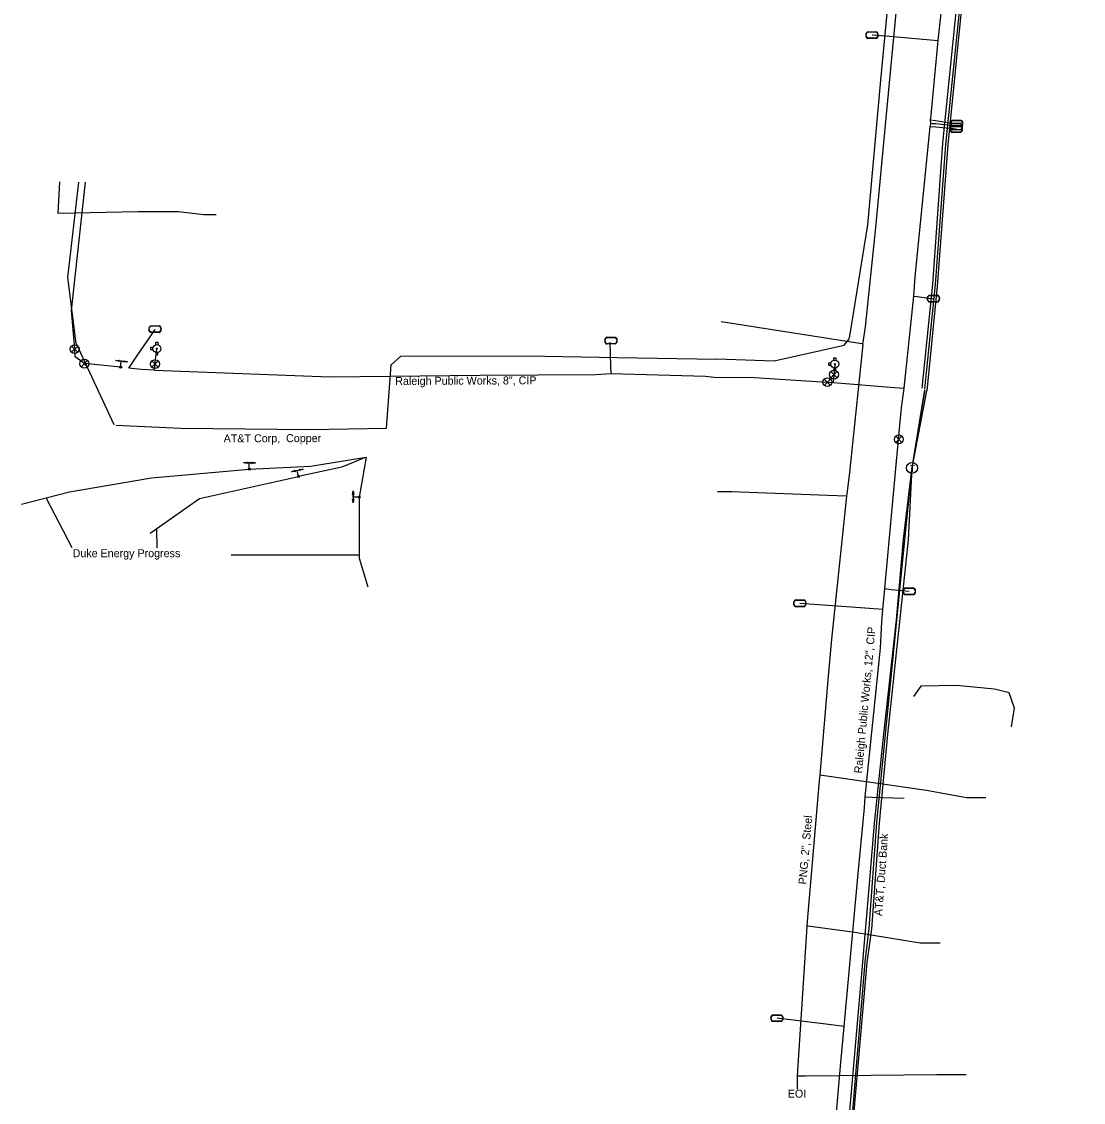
# Model space of a CAD drawing. Extents: x 2070721 to 2083039, y 729290 to 737883.
# Drawn here: x 2081990 to 2082520, y 736699 to 737239 of the extents above; entities that cross this region are included whole.
import ezdxf

# ---------------------------------------------------------------- set-up
doc = ezdxf.new("R2010")
doc.units = 0
for name, color, linetype in [('COGO Default Point Elevation', 7, 'Continuous'), ('COGO Default Point Number', 7, 'Continuous'), ('Exist Utilities Gas UG Line SUE Cogo Point CELL', 7, 'Continuous'), ('Exist Utilities Gas UG Line SUE LOS B Cogo Comment', 7, 'Continuous'), ('Exist Utilities Power Pole CELL', 7, 'Continuous'), ('Exist Utilities Power Pole Cogo Elevation', 7, 'Continuous'), ('Exist Utilities Power UG Cable Cogo Point CELL', 7, 'Continuous'), ('Exist Utilities Power UG Cable SUE LOS B Cogo Elevation', 7, 'Continuous'), ('Exist Utilities Power UG Cable SUE LOS B Cogo Number', 7, 'Continuous'), ('Exist Utilities Telephone Hand Hole Cogo Number', 7, 'Continuous'), ('Exist Utilities Telephone Manhole CELL', 7, 'Continuous'), ('Exist Utilities Telephone UG Cable SUE LOS C Cogo Point CELL', 7, 'Continuous'), ('Exist Utilities Telephone UG FO Cogo Point CELL', 7, 'Continuous'), ('Exist Utilities TV Pedestal Cogo Elevation', 7, 'Continuous'), ('Exist Utilities TV Pedestal Cogo Number', 7, 'Continuous'), ('Exist Utilities TV UG Cable Cogo Point CELL', 7, 'Continuous'), ('Exist Utilities TV UG Cable SUE LOS C Cogo Comment', 7, 'Continuous'), ('Exist Utilities TV UG Cable SUE LOS C Cogo Point CELL', 7, 'Continuous'), ('Exist Utilities Water Meter Cogo Elevation', 7, 'Continuous'), ('Exist Utilities Water Meter Cogo Number', 7, 'Continuous')]:
    doc.layers.add(name, color=color, linetype=linetype)

msp = doc.modelspace()

# ---------------------------------------------------------------- linework, layer by layer
at = {"layer": 'COGO Default Point Elevation'}
for points in [[(2082017.65, 737077.06), (2082014.5, 737073.91), (2082016.07, 737075.48), (2082017.65, 737073.91), (2082014.5, 737077.06)], [(2082022.46, 737069.81), (2082019.3, 737066.66), (2082020.88, 737068.23), (2082022.46, 737066.66), (2082019.3, 737069.81)], [(2082057.81, 737069.57), (2082054.67, 737066.42), (2082056.24, 737067.99), (2082057.81, 737066.42), (2082054.67, 737069.57)], [(2082397.16, 737064.34), (2082394.01, 737061.19), (2082395.59, 737062.77), (2082397.16, 737061.19), (2082394.01, 737064.34)], [(2082393.85, 737060.55), (2082390.7, 737057.4), (2082392.28, 737058.98), (2082393.85, 737057.4), (2082390.7, 737060.55)], [(2082429.58, 737031.97), (2082426.43, 737028.82), (2082428, 737030.39), (2082429.58, 737028.82), (2082426.43, 737031.97)]]:
    msp.add_lwpolyline(points, dxfattribs=at)
for centre in [(2082016.07, 737075.48), (2082020.88, 737068.23), (2082056.24, 737067.99), (2082392.28, 737058.98), (2082395.59, 737062.77), (2082428, 737030.39)]:
    msp.add_circle(centre, 2.23, dxfattribs=at)
at = {"layer": 'COGO Default Point Number'}
for p, q in [((2082057.16, 737075.79), (2082057.16, 737075.79)), ((2082395.99, 737068), (2082395.99, 737068))]:
    msp.add_line(p, q, dxfattribs=at)
for points in [[(2082056.65, 737077.7), (2082056.65, 737078.99), (2082057.67, 737078.99), (2082057.67, 737077.68)], [(2082055.25, 737076.3), (2082053.96, 737076.3), (2082053.96, 737075.28), (2082055.25, 737075.28)], [(2082056.65, 737073.88), (2082056.65, 737072.59), (2082057.67, 737072.59), (2082057.67, 737073.9)], [(2082394.08, 737068.52), (2082392.79, 737068.52), (2082392.79, 737067.49), (2082394.08, 737067.49)], [(2082395.48, 737069.92), (2082395.48, 737071.2), (2082396.5, 737071.2), (2082396.5, 737069.89)], [(2082395.48, 737066.09), (2082395.48, 737064.8), (2082396.5, 737064.8), (2082396.5, 737066.12)]]:
    msp.add_lwpolyline(points, dxfattribs=at)
for centre, radius in [((2082057.16, 737075.79), 1.98), ((2082057.16, 737075.79), 0.243), ((2082395.99, 737068), 1.98), ((2082395.99, 737068), 0.243)]:
    msp.add_circle(centre, radius, dxfattribs=at)
at = {"layer": 'Exist Utilities Power Pole CELL'}
for points in [[(2082439.59, 737056.02), (2082445.06, 737108.02), (2082449.98, 737178.42), (2082461.23, 737288.47), (2082468.24, 737363.11), (2082475.86, 737428.31), (2082486.51, 737547.46), (2082488.71, 737576.37), (2082496.01, 737653.67), (2082500.6, 737701.89), (2082514.35, 737824.3), (2082518.96, 737879.18)], [(2082442.18, 737054.68), (2082447.39, 737106.94), (2082452.67, 737177.7), (2082463.63, 737288.2), (2082470.01, 737364.08), (2082471.45, 737371.14), (2082477.93, 737428.92), (2082490.82, 737576.45), (2082502.28, 737701.6), (2082515.51, 737824.17), (2082520.25, 737879.05)], [(2082396.3, 736612.75), (2082410.09, 736769.04), (2082413.73, 736812.06), (2082415.9, 736838.6), (2082420.43, 736883.01), (2082426.83, 736940.19), (2082430.34, 736980.56), (2082434.54, 737015.35), (2082440.98, 737055.09)], [(2082398.47, 736612.36), (2082412.17, 736768.95), (2082414.49, 736785.54), (2082418.32, 736838.61), (2082422.49, 736882.86), (2082432.87, 736980.11), (2082434.6, 737016.15), (2082441.99, 737054.65)]]:
    msp.add_lwpolyline(points, dxfattribs=at)
at = {"layer": 'Exist Utilities Power Pole Cogo Elevation'}
for points in [[(2081989.55, 736997.93), (2082013.53, 737004.14), (2082054.43, 737011.2), (2082103.34, 737015.52)], [(2082053.87, 736983.53), (2082078.41, 737000.75), (2082127.92, 737011.84)], [(2082158.3, 737001.5), (2082158.3, 736971.08), (2082162.61, 736956.68)]]:
    msp.add_lwpolyline(points, dxfattribs=at)
at = {"layer": 'Exist Utilities Power UG Cable Cogo Point CELL'}
for p, q in [((2082106.48, 737018.6), (2082100.51, 737018.6)), ((2082103.34, 737015.52), (2082103.34, 737018.6)), ((2082103.34, 737018.6), (2082106.48, 737018.6)), ((2082103.34, 737015.52), (2082103.34, 737015.52)), ((2082130.31, 737015.54), (2082124.49, 737014.23)), ((2082127.25, 737014.85), (2082130.31, 737015.54)), ((2082127.92, 737011.84), (2082127.25, 737014.85)), ((2082127.92, 737011.84), (2082127.92, 737011.84)), ((2082155.22, 737001.5), (2082155.22, 737004.64)), ((2082155.22, 737004.64), (2082155.22, 736998.67)), ((2082158.3, 737001.5), (2082155.22, 737001.5)), ((2082158.3, 737001.5), (2082158.3, 737001.5))]:
    msp.add_line(p, q, dxfattribs=at)
for points in [[(2082100.51, 737018.6), (2082102.48, 737018.95), (2082102.06, 737018.6), (2082102.45, 737018.3)], [(2082106.48, 737018.6), (2082104.5, 737018.26), (2082104.92, 737018.6), (2082104.54, 737018.91)], [(2082124.49, 737014.23), (2082126.34, 737015), (2082126, 737014.57), (2082126.44, 737014.36)], [(2082130.31, 737015.54), (2082128.46, 737014.77), (2082128.79, 737015.2), (2082128.35, 737015.41)], [(2082155.22, 737004.64), (2082155.56, 737002.66), (2082155.22, 737003.08), (2082154.91, 737002.7)], [(2082155.22, 736998.67), (2082154.87, 737000.64), (2082155.22, 737000.22), (2082155.52, 737000.61)]]:
    msp.add_lwpolyline(points, close=True, dxfattribs=at)
for centre in [(2082103.34, 737015.52), (2082127.92, 737011.84), (2082158.3, 737001.5)]:
    msp.add_circle(centre, 0.517, dxfattribs=at)
at = {"layer": 'Exist Utilities Power UG Cable SUE LOS B Cogo Number'}
for p, q in [((2082042.46, 737069.23), (2082036.53, 737069.82)), ((2082039.04, 737066.47), (2082039.34, 737069.54)), ((2082039.04, 737066.47), (2082039.04, 737066.47)), ((2082039.34, 737069.54), (2082042.46, 737069.23))]:
    msp.add_line(p, q, dxfattribs=at)
for points in [[(2082036.53, 737069.82), (2082038.52, 737069.97), (2082038.07, 737069.67), (2082038.42, 737069.32)], [(2082042.46, 737069.23), (2082040.47, 737069.08), (2082040.92, 737069.39), (2082040.57, 737069.73)]]:
    msp.add_lwpolyline(points, close=True, dxfattribs=at)
msp.add_circle((2082039.04, 737066.47), 0.517, dxfattribs=at)
at = {"layer": 'Exist Utilities Telephone Manhole CELL'}
for p, q in [((2082001.89, 737001.08), (2082014.59, 736976.38)), ((2082056.94, 736985.67), (2082057.14, 736976.21)), ((2082158.14, 736972.49), (2082094.25, 736972.49))]:
    msp.add_line(p, q, dxfattribs=at)
at = {"layer": 'Exist Utilities Telephone UG Cable SUE LOS C Cogo Point CELL'}
msp.add_circle((2082434.58, 737016.09), 2.72, dxfattribs=at)
at = {"layer": 'Exist Utilities Telephone UG FO Cogo Point CELL'}
for p, q in [((2082414.6, 737232.48), (2082414.6, 737232.48)), ((2082456.69, 737185.53), (2082456.69, 737185.53)), ((2082456.72, 737186.75), (2082456.72, 737186.75)), ((2082456.91, 737188.26), (2082456.91, 737188.26)), ((2082445.29, 737100.75), (2082445.29, 737100.75)), ((2082056.25, 737085.51), (2082056.25, 737085.51)), ((2082284.14, 737079.77), (2082284.14, 737079.77)), ((2082433.24, 736954.42), (2082433.24, 736954.42)), ((2082378.52, 736948.43), (2082378.52, 736948.43)), ((2082367.09, 736741.04), (2082367.09, 736741.04))]:
    msp.add_line(p, q, dxfattribs=at)
for points in [[(2082412.56, 737234.18), (2082416.63, 737234.18)], [(2082412.56, 737234.04), (2082416.63, 737234.04)], [(2082416.63, 737230.92), (2082412.53, 737230.92)], [(2082416.63, 737230.78), (2082412.53, 737230.78)], [(2082454.66, 737187.23), (2082458.73, 737187.23)], [(2082454.66, 737187.09), (2082458.73, 737187.09)], [(2082458.76, 737185.18), (2082454.66, 737185.18)], [(2082458.76, 737185.05), (2082454.66, 737185.05)], [(2082454.68, 737188.45), (2082458.76, 737188.45)], [(2082454.68, 737188.31), (2082458.76, 737188.31)], [(2082458.95, 737186.7), (2082454.85, 737186.7)], [(2082458.95, 737186.56), (2082454.85, 737186.56)], [(2082454.87, 737189.96), (2082458.95, 737189.96)], [(2082454.87, 737189.83), (2082458.95, 737189.83)], [(2082458.73, 737183.97), (2082454.63, 737183.97)], [(2082458.73, 737183.83), (2082454.63, 737183.83)], [(2082447.33, 737099.19), (2082443.23, 737099.19)], [(2082447.33, 737099.05), (2082443.23, 737099.05)], [(2082443.25, 737102.45), (2082447.33, 737102.45)], [(2082443.25, 737102.31), (2082447.33, 737102.31)], [(2082058.29, 737083.95), (2082054.19, 737083.95)], [(2082058.29, 737083.81), (2082054.19, 737083.81)], [(2082054.21, 737087.21), (2082058.29, 737087.21)], [(2082054.21, 737087.07), (2082058.29, 737087.07)], [(2082286.18, 737078.21), (2082282.08, 737078.21)], [(2082286.18, 737078.07), (2082282.08, 737078.07)], [(2082282.1, 737081.47), (2082286.18, 737081.47)], [(2082282.1, 737081.33), (2082286.18, 737081.33)], [(2082435.28, 736952.86), (2082431.18, 736952.86)], [(2082435.28, 736952.72), (2082431.18, 736952.72)], [(2082431.2, 736956.12), (2082435.28, 736956.12)], [(2082431.2, 736955.98), (2082435.28, 736955.98)], [(2082376.48, 736950.13), (2082380.56, 736950.13)], [(2082376.48, 736950), (2082380.56, 736950)], [(2082380.56, 736946.87), (2082376.46, 736946.87)], [(2082380.56, 736946.73), (2082376.46, 736946.73)], [(2082365.05, 736742.74), (2082369.13, 736742.74)], [(2082365.05, 736742.6), (2082369.13, 736742.6)], [(2082369.13, 736739.48), (2082365.03, 736739.48)], [(2082369.13, 736739.34), (2082365.03, 736739.34)]]:
    msp.add_lwpolyline(points, dxfattribs=at)
for centre, radius, start, end in [((2082413.29, 737232.47), 1.86, 113.178, 245.9794), ((2082413.3, 737232.47), 1.73, 115.3009, 243.7824), ((2082415.89, 737232.48), 1.86, 293.6483, 66.3084), ((2082415.9, 737232.48), 1.73, 295.1272, 64.8728), ((2082455.39, 737185.53), 1.86, 113.178, 245.9794), ((2082455.41, 737186.74), 1.86, 113.178, 245.9794), ((2082455.4, 737185.53), 1.73, 115.3009, 243.7824), ((2082455.42, 737186.74), 1.73, 115.3009, 243.7824), ((2082455.6, 737188.26), 1.86, 113.178, 245.9794), ((2082455.61, 737188.26), 1.73, 115.3009, 243.7824), ((2082457.99, 737185.53), 1.86, 293.6483, 66.3084), ((2082458, 737185.53), 1.73, 295.1272, 64.8728), ((2082458.01, 737186.75), 1.86, 293.6483, 66.3084), ((2082458.02, 737186.75), 1.73, 295.1272, 64.8728), ((2082458.2, 737188.26), 1.86, 293.6483, 66.3084), ((2082458.22, 737188.26), 1.73, 295.1272, 64.8728), ((2082443.98, 737100.74), 1.86, 113.178, 245.9794), ((2082443.99, 737100.74), 1.73, 115.3009, 243.7824), ((2082446.58, 737100.75), 1.86, 293.6483, 66.3084), ((2082446.59, 737100.75), 1.73, 295.1272, 64.8728), ((2082054.94, 737085.5), 1.86, 113.178, 245.9794), ((2082054.95, 737085.5), 1.73, 115.3009, 243.7824), ((2082057.54, 737085.51), 1.86, 293.6483, 66.3084), ((2082057.55, 737085.51), 1.73, 295.1272, 64.8728), ((2082282.83, 737079.76), 1.86, 113.178, 245.9794), ((2082282.84, 737079.76), 1.73, 115.3009, 243.7824), ((2082285.43, 737079.77), 1.86, 293.6483, 66.3084), ((2082285.44, 737079.77), 1.73, 295.1272, 64.8728), ((2082431.93, 736954.41), 1.86, 113.178, 245.9794), ((2082431.94, 736954.41), 1.73, 115.3009, 243.7824), ((2082434.53, 736954.42), 1.86, 293.6483, 66.3084), ((2082434.54, 736954.42), 1.73, 295.1272, 64.8728), ((2082377.21, 736948.43), 1.86, 113.178, 245.9794), ((2082377.22, 736948.43), 1.73, 115.3009, 243.7824), ((2082379.81, 736948.43), 1.86, 293.6483, 66.3084), ((2082379.82, 736948.43), 1.73, 295.1272, 64.8728), ((2082365.78, 736741.03), 1.86, 113.178, 245.9794), ((2082365.79, 736741.03), 1.73, 115.3009, 243.7824), ((2082368.38, 736741.04), 1.86, 293.6483, 66.3084), ((2082368.39, 736741.04), 1.73, 295.1272, 64.8728)]:
    msp.add_arc(centre, radius, start, end, dxfattribs=at)
at = {"layer": 'Exist Utilities TV Pedestal Cogo Elevation'}
msp.add_line((2082395.41, 737058.76), (2082396.16, 737068), dxfattribs=at)
for points in [[(2082443.82, 737190.2), (2082444.22, 737192.46), (2082447.74, 737229.76), (2082454.53, 737292.18)], [(2082414.68, 737232.54), (2082421.58, 737232.04), (2082447.56, 737229.86)], [(2082435.52, 737101.94), (2082436.16, 737111.62), (2082443.68, 737186.87), (2082443.92, 737188.12), (2082443.82, 737190.2)], [(2082443.68, 737186.87), (2082446.48, 737186.62), (2082456.71, 737185.63)], [(2082443.82, 737190.2), (2082446.35, 737189.78), (2082456.88, 737188.05)], [(2082456.54, 737186.96), (2082446.46, 737188.11), (2082443.92, 737188.12)], [(2082039.04, 737066.47), (2082020.95, 737068.25), (2082016.32, 737071.67), (2082016.09, 737075.58), (2082014.49, 737094.86), (2082021.55, 737158.93)], [(2082430.73, 737055.97), (2082435.52, 737101.94)], [(2082435.52, 737101.94), (2082437.12, 737101.74), (2082445.22, 737100.72)], [(2082043.13, 737066.04), (2082046.82, 737071.41), (2082056.38, 737085.32)], [(2082284.15, 737063.3), (2082284.05, 737066.83), (2082283.7, 737078.9)], [(2082055.89, 737064.98), (2082056.36, 737068.94), (2082057.12, 737075.64)], [(2082055.89, 737064.98), (2082049.25, 737065.33), (2082043.13, 737066.04)], [(2082055.89, 737064.98), (2082143.58, 737061.72), (2082218.78, 737062.44), (2082276.4, 737062.74), (2082284.15, 737063.3)], [(2082284.15, 737063.3), (2082331.37, 737061.93), (2082335.5, 737061.51)], [(2082335.5, 737061.51), (2082355.64, 737061.26), (2082392.26, 737059.03), (2082395.39, 737058.76), (2082423.61, 737056.45), (2082430.73, 737055.97)], [(2082421, 736955.83), (2082427.79, 737030.39), (2082429.41, 737046.22), (2082430.73, 737055.97)], [(2082419.94, 736945.35), (2082420.45, 736950.54), (2082421, 736955.83)], [(2082421, 736955.83), (2082424.1, 736955.42), (2082433.2, 736954.48)], [(2082419.94, 736945.35), (2082408.88, 736946.2), (2082378.56, 736948.3)], [(2082411.18, 736851.65), (2082418.88, 736926.06), (2082419.48, 736939.21), (2082419.94, 736945.35)], [(2082400.72, 736736.91), (2082407.72, 736813.44), (2082410.77, 736846.16), (2082411.18, 736851.65)], [(2082411.18, 736851.65), (2082414.7, 736851.47), (2082430.7, 736850.96)], [(2082400.72, 736736.91), (2082392.83, 736737.84), (2082367.14, 736740.99)], [(2082384.35, 736558.86), (2082384.46, 736561.59), (2082391.2, 736628.12), (2082394.55, 736666.82), (2082398.88, 736717.07), (2082400.72, 736736.91)]]:
    msp.add_lwpolyline(points, dxfattribs=at)
at = {"layer": 'Exist Utilities TV Pedestal Cogo Number'}
for points in [[(2082410, 737077.78), (2082411.36, 737086.72), (2082416.51, 737136.35), (2082423.37, 737208.61), (2082428.12, 737259.46)], [(2082086.81, 737142.62), (2082080.65, 737142.62), (2082067.93, 737144.1), (2082047.64, 737144.1), (2082007.79, 737143.29), (2082008.6, 737159.16)], [(2082410.05, 737078.11), (2082409.57, 737078.19), (2082339.15, 737089.12)], [(2082410, 737077.78), (2082403.4, 737013.84), (2082401.98, 737003.02), (2082401.84, 737001.99)], [(2082401.84, 737001.99), (2082392.37, 737002.41), (2082344.59, 737004.1), (2082337.38, 737004.1)], [(2082401.84, 737001.99), (2082394.29, 736930.45), (2082392.69, 736912.07), (2082388.57, 736862.67), (2082388.2, 736859.67)], [(2082388.57, 736862.67), (2082390.79, 736862.35), (2082441.82, 736854.95), (2082461.89, 736851.41), (2082471.48, 736851.41)], [(2082388.2, 736859.67), (2082382.07, 736787.6), (2082382.04, 736786.95)], [(2082382.04, 736786.95), (2082377.25, 736712.27), (2082377.25, 736705.53)], [(2082382.06, 736787.27), (2082382.54, 736787.14), (2082405.93, 736783.98), (2082438.62, 736778.77), (2082448.61, 736778.77)], [(2082377.25, 736712.27), (2082381.16, 736712.31), (2082447.01, 736712.93), (2082461.69, 736712.93)]]:
    msp.add_lwpolyline(points, dxfattribs=at)
at = {"layer": 'Exist Utilities TV UG Cable Cogo Point CELL'}
for points in [[(2082403.44, 737082.03), (2082412.57, 737137.7), (2082418.97, 737209.91), (2082421.82, 737239.88), (2082432.43, 737345.64), (2082437.88, 737400.24), (2082446.55, 737496.08), (2082457.15, 737602.73), (2082463.04, 737658.16), (2082480.56, 737850.96), (2082483.62, 737882.51)], [(2082017.92, 737159), (2082012.49, 737111.23), (2082016.64, 737078.39), (2082016.82, 737078.34), (2082035.62, 737037.81)], [(2082337.01, 737070.62), (2082365.7, 737069.73), (2082400.6, 737077.49), (2082403.07, 737080.36), (2082403.44, 737082.03)], [(2082036.57, 737037.57), (2082069.13, 737035.95), (2082133.69, 737035.26), (2082171.93, 737035.92), (2082174.2, 737067.68), (2082179.11, 737071.93), (2082242.14, 737072.12), (2082287.24, 737071.24), (2082337.04, 737070.55)]]:
    msp.add_lwpolyline(points, dxfattribs=at)
at = {"layer": 'Exist Utilities TV UG Cable SUE LOS C Cogo Comment'}
msp.add_line((2082161.82, 737021.41), (2082158.3, 737001.5), dxfattribs=at)
for points in [[(2082103.34, 737015.52), (2082133.96, 737017.04), (2082161.75, 737021.48)], [(2082160.93, 737021.21), (2082149.62, 737016.5), (2082127.92, 737011.84)], [(2082484.4, 736886.67), (2082485.88, 736896.06), (2082483.16, 736903.73), (2082475.75, 736905.58), (2082456.82, 736907.35), (2082438.93, 736906.94), (2082435.27, 736901.85)]]:
    msp.add_lwpolyline(points, dxfattribs=at)
at = {"layer": 'Exist Utilities TV UG Cable SUE LOS C Cogo Point CELL'}
for points in [[(2082440.99, 737055.64), (2082446.34, 737107.79), (2082451.46, 737177.85), (2082462.75, 737288.32), (2082470.03, 737364.09), (2082470.98, 737371.16), (2082477.18, 737429.09), (2082489.87, 737576.45), (2082501.4, 737701.55), (2082515.01, 737823.97), (2082519.76, 737879.1)], [(2082398.1, 736612.48), (2082411.1, 736769.26), (2082413.2, 736785.84), (2082417.08, 736838.79), (2082421.4, 736882.93), (2082431.06, 736980.24), (2082434.68, 737016.11), (2082441.24, 737055.15)]]:
    msp.add_lwpolyline(points, dxfattribs=at)

# ---------------------------------------------------------------- texts
at = {"layer": 'Exist Utilities Gas UG Line SUE Cogo Point CELL'}
for s, rotation, p in [('Raleigh Public Works, 8", CIP ', 0.2987, (2082176.32, 737057.56)), ('Raleigh Public Works, 12", CIP ', 84.6792, (2082409.6, 736863.27))]:
    msp.add_text(s, height=4, rotation=rotation, dxfattribs=at).set_placement(p)
at = {"layer": 'Exist Utilities Gas UG Line SUE LOS B Cogo Comment'}
msp.add_text('AT&T, Duct Bank', height=4, rotation=85.8017, dxfattribs=at).set_placement((2082419.66, 736791.99))
at = {"layer": 'Exist Utilities Power UG Cable SUE LOS B Cogo Elevation'}
msp.add_text('EOI', height=4, dxfattribs=at).set_placement((2082372.49, 736701.33))
at = {"layer": 'Exist Utilities Telephone Hand Hole Cogo Number'}
msp.add_text('Duke Energy Progress', height=4, dxfattribs=at).set_placement((2082015.05, 736971.49))
at = {"layer": 'Exist Utilities Telephone UG Cable SUE LOS C Cogo Point CELL'}
msp.add_text('T', height=3.5, dxfattribs=at).set_placement((2082433.4, 737014.08))
at = {"layer": 'Exist Utilities Water Meter Cogo Elevation'}
msp.add_text('PNG, 2", Steel', height=4, rotation=85.1413, dxfattribs=at).set_placement((2082381.78, 736807.77))
at = {"layer": 'Exist Utilities Water Meter Cogo Number'}
msp.add_text('AT&T Corp,  Copper', height=4, rotation=0.1727, dxfattribs=at).set_placement((2082090.55, 737028.88))

doc.saveas('drawing.dxf')
